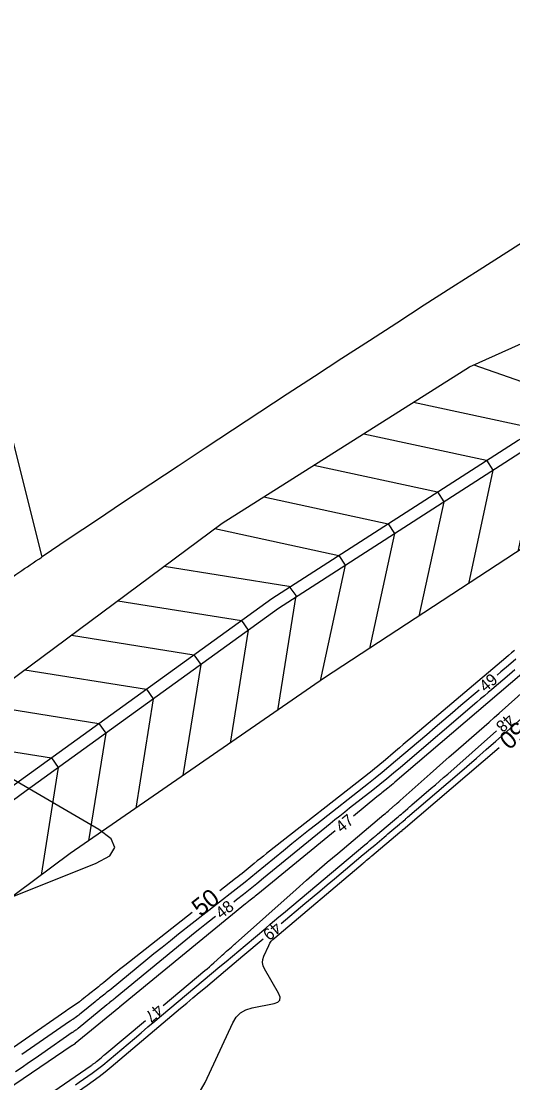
# Model space of a CAD drawing. Extents: x 2384780 to 2405861, y 547869 to 573706.
# Drawn here: x 2392601.5 to 2392685.5, y 553648.5 to 553830.1 of the extents above; entities that cross this region are included whole.
import ezdxf

# ---------------------------------------------------------------- set-up
doc = ezdxf.new("R2010")
doc.units = 0
for name, color, linetype in [('Old_Level_60', 7, 'Continuous'), ('Old_Level_61', 7, 'Continuous'), ('Old_Level_63', 7, 'Continuous'), ('Sheet Plan CELL', 7, 'Continuous')]:
    doc.layers.add(name, color=color, linetype=linetype)

msp = doc.modelspace()

# ---------------------------------------------------------------- linework, layer by layer
at = {"layer": 'Old_Level_60'}
for points in [[(2392686.04425, 553721.00125), (2392684.77, 553719.9185), (2392683.49475, 553718.837), (2392682.8395, 553718.28175)], [(2392625.80325, 553661.76), (2392632.9185, 553667.73625), (2392633.297, 553668.05775), (2392633.6715, 553668.38325), (2392634.0425, 553668.71275), (2392634.41, 553669.04675), (2392635.62225, 553670.16075), (2392635.87, 553670.3865), (2392636.11975, 553670.61), (2392636.37125, 553670.83175), (2392636.62475, 553671.051), (2392637.45575, 553671.76425), (2392637.63325, 553671.91775), (2392637.81025, 553672.07175), (2392637.98625, 553672.227), (2392638.16175, 553672.38275), (2392648.49925, 553681.6255), (2392650.25525, 553683.18325), (2392652.02375, 553684.72675), (2392653.80425, 553686.25625), (2392655.59675, 553687.77175), (2392663.5015, 553694.401), (2392663.74575, 553694.60675), (2392663.98875, 553694.8135), (2392664.231, 553695.02175), (2392664.472, 553695.231), (2392665.4205, 553696.05825), (2392665.5075, 553696.13425), (2392665.59475, 553696.21025), (2392665.68175, 553696.28625), (2392665.7685, 553696.3625), (2392666.05275, 553696.61125), (2392666.1135, 553696.6645), (2392666.174, 553696.71825), (2392666.2345, 553696.772), (2392666.295, 553696.82575), (2392671.3795, 553701.38025), (2392672.4705, 553702.3545), (2392673.56425, 553703.3255), (2392674.66125, 553704.293), (2392675.761, 553705.25725), (2392679.75275, 553708.7465), (2392680.60725, 553709.49525), (2392681.45975, 553710.246), (2392682.31025, 553710.99925), (2392683.15875, 553711.7545), (2392691.17, 553718.90425)], [(2392685.88025, 553719.15675), (2392684.9595, 553718.37575), (2392681.95025, 553715.8265), (2392681.30575, 553715.28), (2392680.66175, 553714.73275), (2392680.018, 553714.185), (2392679.375, 553713.6365), (2392666.32225, 553702.494), (2392665.15, 553701.5035), (2392663.96775, 553700.525), (2392662.77575, 553699.5585), (2392661.574, 553698.60425), (2392657.63175, 553695.506), (2392656.78875, 553694.84), (2392655.94925, 553694.16975), (2392655.113, 553693.49525), (2392654.28, 553692.8165), (2392642.94275, 553683.5295), (2392641.7925, 553682.5925), (2392640.6375, 553681.66125), (2392639.47775, 553680.73625), (2392638.313, 553679.81725), (2392637.83725, 553679.44375)], [(2392687.07525, 553718.46275), (2392665.36675, 553699.9315), (2392665.068, 553699.679), (2392664.76675, 553699.42975), (2392664.463, 553699.18325), (2392664.15675, 553698.94), (2392663.152, 553698.1505), (2392662.93725, 553697.98075), (2392662.72325, 553697.81), (2392662.51025, 553697.638), (2392662.298, 553697.46525), (2392658.2695, 553694.16525)], [(2392679.7875, 553715.69625), (2392676.655, 553713.04275), (2392675.19, 553711.8005), (2392673.72625, 553710.55675), (2392672.2635, 553709.3115), (2392670.802, 553708.06525), (2392665.48275, 553703.5245), (2392664.33825, 553702.55725), (2392663.184, 553701.602), (2392662.02, 553700.65825), (2392660.8465, 553699.7265), (2392652.02725, 553692.795), (2392650.59825, 553691.666), (2392649.17475, 553690.52975), (2392647.757, 553689.38625), (2392646.34525, 553688.23575), (2392641.74225, 553684.46525), (2392640.75375, 553683.66), (2392639.76125, 553682.85975), (2392638.7645, 553682.06475), (2392637.76375, 553681.275), (2392628.42375, 553673.9435), (2392627.013, 553672.83), (2392625.60825, 553671.709), (2392624.20975, 553670.5805), (2392622.81725, 553669.44425), (2392616.867, 553664.563), (2392616.59925, 553664.3445), (2392616.33025, 553664.12775), (2392616.06025, 553663.9125), (2392615.789, 553663.6985), (2392614.901, 553663.0025), (2392614.711, 553662.85275), (2392614.522, 553662.702), (2392614.33375, 553662.55025), (2392614.1465, 553662.39725), (2392611.75025, 553660.43125), (2392611.56075, 553660.27875), (2392611.368, 553660.13025), (2392611.17225, 553659.9855), (2392610.97375, 553659.84475), (2392610.32025, 553659.391), (2392610.18, 553659.294), (2392610.04, 553659.19675), (2392609.9, 553659.0995), (2392609.76, 553659.00225), (2392601.639, 553653.36625)], [(2392645.94425, 553675.768), (2392650.00025, 553679.1915), (2392651.26125, 553680.255), (2392652.52275, 553681.31775), (2392653.785, 553682.3795), (2392655.048, 553683.44075), (2392659.96875, 553687.5725), (2392660.456, 553687.98175), (2392660.94275, 553688.39125), (2392661.4295, 553688.80125), (2392661.916, 553689.21125), (2392663.512, 553690.558), (2392663.84875, 553690.842), (2392664.1855, 553691.12575), (2392664.5225, 553691.40925), (2392664.85975, 553691.6925), (2392666.15375, 553692.77875), (2392666.2935, 553692.897), (2392666.43225, 553693.016), (2392666.57025, 553693.136), (2392666.7075, 553693.257), (2392667.15425, 553693.65375), (2392667.25, 553693.7385), (2392667.3465, 553693.82275), (2392667.443, 553693.90675), (2392667.54025, 553693.99), (2392676.0125, 553701.23125), (2392677.67225, 553702.65675), (2392679.3255, 553704.0895), (2392680.97175, 553705.53025), (2392682.6115, 553706.9785), (2392687.95725, 553711.722)], [(2392610.778, 553648.179), (2392611.45125, 553648.64725), (2392613.649, 553650.17825), (2392614.116, 553650.5115), (2392614.57475, 553650.8555), (2392615.0255, 553651.20975), (2392615.468, 553651.57475), (2392620.86825, 553656.13425), (2392622.02575, 553657.11075), (2392623.184, 553658.08675), (2392624.34275, 553659.06175), (2392625.502, 553660.03625), (2392635.46475, 553668.40425), (2392636.5445, 553669.3115), (2392637.62375, 553670.2195), (2392638.70225, 553671.12825), (2392639.78025, 553672.03775), (2392643.30125, 553675.00925), (2392644.05575, 553675.64575), (2392644.81075, 553676.28175), (2392645.56625, 553676.9175), (2392646.32225, 553677.5525), (2392660.24075, 553689.239), (2392660.45325, 553689.4175), (2392660.6655, 553689.596), (2392660.8775, 553689.77475), (2392661.08975, 553689.9535), (2392661.78225, 553690.53775), (2392661.93075, 553690.663), (2392662.07925, 553690.788), (2392662.22775, 553690.913), (2392662.3765, 553691.038), (2392665.723, 553693.8475), (2392665.9815, 553694.06625), (2392666.2385, 553694.2865), (2392666.49375, 553694.50875), (2392666.74775, 553694.7325), (2392667.57475, 553695.467), (2392667.75225, 553695.624), (2392667.9305, 553695.78), (2392668.1095, 553695.93525), (2392668.2895, 553696.08975), (2392671.58575, 553698.907), (2392672.2905, 553699.51225), (2392672.99275, 553700.121), (2392673.692, 553700.73275), (2392674.3885, 553701.348), (2392682.702, 553708.72525)], [(2392655.175, 553691.6305), (2392641.934, 553680.7845), (2392641.729, 553680.61725), (2392641.523, 553680.45125), (2392641.31625, 553680.28625), (2392641.1085, 553680.1225), (2392640.42875, 553679.58875), (2392640.2835, 553679.47425), (2392640.13875, 553679.35875), (2392639.99475, 553679.24225), (2392639.85125, 553679.12525), (2392618.3235, 553661.465), (2392618.3115, 553661.45525), (2392618.29975, 553661.44575), (2392618.288, 553661.43625), (2392618.276, 553661.427), (2392618.237, 553661.39625), (2392618.2285, 553661.38975), (2392618.22025, 553661.383), (2392618.212, 553661.3765), (2392618.20375, 553661.36975), (2392610.767, 553655.26775), (2392610.76225, 553655.264), (2392610.7575, 553655.26025), (2392610.75275, 553655.2565), (2392610.74775, 553655.253), (2392610.7315, 553655.24175), (2392610.728, 553655.2395), (2392610.7245, 553655.237), (2392610.721, 553655.2345), (2392610.7175, 553655.23225), (2392610.4645, 553655.0565), (2392610.41025, 553655.019), (2392610.356, 553654.9815), (2392610.3015, 553654.94425), (2392610.247, 553654.907), (2392586.49075, 553638.7635)], [(2392634.69075, 553676.974), (2392634.50075, 553676.82475), (2392633.6855, 553676.18125), (2392632.87375, 553675.5335), (2392632.06575, 553674.88125), (2392631.261, 553674.22475), (2392617.59525, 553663.014), (2392617.4555, 553662.9), (2392617.315, 553662.78675), (2392617.174, 553662.67425), (2392617.0325, 553662.56275), (2392616.569, 553662.19925), (2392616.46975, 553662.12125), (2392616.371, 553662.0425), (2392616.27275, 553661.96325), (2392616.175, 553661.8835), (2392611.25875, 553657.8495), (2392611.1615, 553657.77125), (2392611.06275, 553657.69525), (2392610.9625, 553657.621), (2392610.86075, 553657.54875), (2392610.52575, 553657.3165), (2392610.454, 553657.26675), (2392610.38225, 553657.21675), (2392610.3105, 553657.167), (2392610.23875, 553657.11725), (2392605.0245, 553653.4985), (2392603.90625, 553652.7245), (2392602.786, 553651.953), (2392601.664, 553651.1845), (2392600.54, 553650.41875)], [(2392600.6475, 553639.7135), (2392601.5345, 553640.3265), (2392602.42275, 553640.938), (2392605.32575, 553642.9335), (2392605.9475, 553643.3615), (2392606.5685, 553643.7905), (2392607.18875, 553644.2205), (2392607.8085, 553644.6515), (2392612.776, 553648.112), (2392613.83125, 553648.8655), (2392614.86825, 553649.64275), (2392615.887, 553650.444), (2392616.8875, 553651.269), (2392628.7615, 553661.294), (2392629.817, 553662.18425), (2392630.87275, 553663.074), (2392631.92925, 553663.96325), (2392632.9865, 553664.85175), (2392636.4405, 553667.75275), (2392637.1805, 553668.37475), (2392637.92, 553668.997), (2392638.65925, 553669.61975), (2392639.398, 553670.243), (2392642.8875, 553673.188)], [(2392590.98725, 553636.0595), (2392613.45025, 553651.4995), (2392613.54575, 553651.56525), (2392613.64125, 553651.63125), (2392613.73675, 553651.6975), (2392613.83225, 553651.76375), (2392614.1435, 553651.9805), (2392614.2095, 553652.02775), (2392614.2745, 553652.0765), (2392614.33825, 553652.12675), (2392614.401, 553652.1785), (2392615.166, 553652.82425), (2392615.32975, 553652.9625), (2392615.49375, 553653.10075), (2392615.658, 553653.23875), (2392615.82225, 553653.37675), (2392622.74025, 553659.1875)]]:
    msp.add_lwpolyline(points, dxfattribs=at)
at = {"layer": 'Old_Level_61'}
for points in [[(2392685.77775, 553722.477), (2392685.2905, 553722.062), (2392684.80275, 553721.6475), (2392684.3145, 553721.2335), (2392668.10175, 553707.49875), (2392667.44475, 553706.9415), (2392666.78825, 553706.38375), (2392666.132, 553705.82525), (2392665.4765, 553705.26625), (2392663.33625, 553703.439), (2392662.8755, 553703.05), (2392662.411, 553702.6655), (2392661.94275, 553702.28575), (2392661.4705, 553701.91075), (2392643.44875, 553687.74675), (2392642.9175, 553687.327), (2392642.38825, 553686.90475), (2392641.86125, 553686.47975), (2392641.3365, 553686.052), (2392639.62525, 553684.65025), (2392639.258, 553684.351), (2392638.889, 553684.0535), (2392638.5185, 553683.758), (2392638.1465, 553683.46425), (2392635.44575, 553681.3445)], [(2392631.5265, 553646.11875), (2392632.926, 553648.58975), (2392637.6605, 553658.77775), (2392638.23725, 553659.73775), (2392638.9785, 553660.48825), (2392639.88425, 553661.02925), (2392640.954, 553661.36075), (2392644.7175, 553662.10175), (2392645.37175, 553662.3295), (2392645.7215, 553662.6955), (2392645.767, 553663.2), (2392645.50825, 553663.8425), (2392643.1005, 553668.01175), (2392642.86325, 553668.54725), (2392642.7665, 553669.08975), (2392642.81, 553669.63925), (2392642.994, 553670.19525), (2392643.824, 553672.02325), (2392644.02075, 553672.40075), (2392644.25525, 553672.7495), (2392644.52725, 553673.07), (2392644.83725, 553673.36175), (2392659.93675, 553686.10625), (2392660.08475, 553686.231), (2392660.23275, 553686.35575), (2392660.381, 553686.48025), (2392660.52925, 553686.60475), (2392661.0135, 553687.01125), (2392661.11725, 553687.0985), (2392661.221, 553687.18575), (2392661.3245, 553687.273), (2392661.428, 553687.3605), (2392666.19125, 553691.37925), (2392666.24125, 553691.4215), (2392666.2915, 553691.46375), (2392666.34175, 553691.506), (2392666.392, 553691.54825), (2392666.5845, 553691.71), (2392666.6055, 553691.72775), (2392666.626, 553691.74525), (2392666.64675, 553691.76325), (2392666.667, 553691.78125), (2392666.7335, 553691.84025), (2392666.748, 553691.853), (2392666.76225, 553691.8655), (2392666.77675, 553691.878), (2392666.791, 553691.8905), (2392683.19325, 553705.9095)], [(2392599.95775, 553680.3725), (2392614.34775, 553686.09475), (2392616.68775, 553687.37675), (2392617.54, 553688.77), (2392616.90475, 553690.2745), (2392614.78175, 553691.8905), (2392599.4685, 553700.82075)], [(2392630.726, 553677.63975), (2392619.234, 553668.619), (2392618.78075, 553668.26125), (2392618.3295, 553667.90125), (2392617.88, 553667.5385), (2392617.43275, 553667.1735), (2392615.97425, 553665.977), (2392615.661, 553665.7215), (2392615.3465, 553665.46775), (2392615.03025, 553665.21575), (2392614.713, 553664.9655), (2392612.97225, 553663.60125), (2392612.8215, 553663.4825), (2392612.67175, 553663.36275), (2392612.52225, 553663.2425), (2392612.37375, 553663.12125), (2392611.8895, 553662.72375), (2392611.78475, 553662.63975), (2392611.67875, 553662.55775), (2392611.57075, 553662.478), (2392611.46125, 553662.4005), (2392610.227, 553661.54375), (2392609.96225, 553661.36025), (2392609.69775, 553661.1765), (2392609.43325, 553660.993), (2392609.16875, 553660.8095), (2392588.40825, 553646.40125)]]:
    msp.add_lwpolyline(points, dxfattribs=at)
at = {"layer": 'Old_Level_63'}
msp.add_lwpolyline([(2392605.1035, 553738.50075), (2392594.60925, 553780.10375), (2392558.996, 553773.963)], dxfattribs=at)
msp.add_arc((2394828.31077, 550434.91596), 3982, 118.79726944, 123.93929722, dxfattribs=at)
msp.add_spline([(2392322.107, 553535.63125), (2392325.8135, 553538.37375), (2392329.521, 553541.1165), (2392333.2305, 553543.86075), (2392336.94225, 553546.60625), (2392340.65775, 553549.3545), (2392344.3735, 553552.102), (2392348.0935, 553554.8525), (2392351.814, 553557.6025), (2392355.53775, 553560.35425), (2392359.26675, 553563.109), (2392362.9945, 553565.86175), (2392366.727, 553568.61725), (2392370.46275, 553571.3735), (2392374.19675, 553574.1275), (2392377.936, 553576.8845), (2392381.68125, 553579.644), (2392385.42425, 553582.4005), (2392389.17375, 553585.1605), (2392392.926, 553587.92025), (2392396.6795, 553590.6795), (2392400.43925, 553593.44125), (2392404.19925, 553596.2015), (2392407.96325, 553598.96225), (2392411.72825, 553601.7215), (2392415.49925, 553604.48325), (2392419.27425, 553607.24525), (2392423.0475, 553610.00375), (2392426.82675, 553612.76425), (2392430.6105, 553615.525), (2392434.39825, 553618.286), (2392438.18925, 553621.04675), (2392441.984, 553623.807), (2392445.781, 553626.566), (2392449.57925, 553629.32275), (2392453.38325, 553632.08075), (2392457.19475, 553634.84075), (2392461.00575, 553637.5965), (2392464.82025, 553640.352), (2392468.64175, 553643.10825), (2392472.46475, 553645.8625), (2392476.2925, 553648.61625), (2392480.12425, 553651.36875), (2392483.961, 553654.12075), (2392487.79725, 553656.8685), (2392491.6425, 553659.619), (2392495.49, 553662.366), (2392499.34225, 553665.11275), (2392503.199, 553667.85775), (2392507.05775, 553670.6), (2392510.9275, 553673.34525), (2392514.7955, 553676.08425), (2392518.669, 553678.82275), (2392522.5455, 553681.55825), (2392526.4285, 553684.29325), (2392530.31675, 553687.027), (2392534.2075, 553689.7575), (2392538.10875, 553692.48975), (2392542.00975, 553695.216), (2392545.91125, 553697.93775), (2392549.823, 553700.661), (2392553.73875, 553703.381), (2392557.66125, 553706.10025), (2392561.58625, 553708.81525), (2392565.51625, 553711.52775), (2392569.452, 553714.238), (2392573.39075, 553716.9445), (2392577.34025, 553719.652), (2392581.29, 553722.353), (2392585.24325, 553725.0505), (2392589.20675, 553727.74825), (2392593.1735, 553730.4415), (2392597.14325, 553733.13), (2392601.12125, 553735.8175), (2392605.02475, 553738.44775)], degree=3, dxfattribs=at)
at = {"layer": 'Sheet Plan CELL'}
for points in [[(2393008.398, 553927.17025), (2392961.427, 553902.4275), (2392917.51975, 553878.505), (2392871.181, 553852.58075), (2392828.0225, 553827.3345), (2392788.076, 553796.64125), (2392737.2995, 553772.17825), (2392695.18775, 553745.21125), (2392653.36, 553717.816), (2392609.89525, 553687.7595), (2392569.78325, 553657.869), (2392527.365, 553625.7965), (2392487.79375, 553595.2155), (2392448.41025, 553564.38), (2392409.161, 553533.36375)], [(2392399.88375, 553545.903), (2392439.06575, 553577.01), (2392478.7045, 553607.50025), (2392518.175, 553638.21775), (2392560.9795, 553670.484), (2392601.23525, 553700.1685), (2392644.36625, 553731.39125), (2392686.40225, 553758.4725), (2392731.9095, 553780.314), (2392779.46625, 553811.242), (2392821.895, 553837.72625), (2392864.53775, 553863.847), (2392910.385, 553891.363), (2392954.08625, 553915.6555)], [(2392401.07325, 553544.29525), (2392440.25525, 553575.40225), (2392479.894, 553605.8925), (2392519.36475, 553636.60975), (2392562.12425, 553668.84375), (2392602.38, 553698.52825), (2392645.471, 553729.72375), (2392687.507, 553756.805), (2392733.0145, 553778.646), (2392780.48225, 553809.51925), (2392822.91075, 553836.0035), (2392865.55375, 553862.124), (2392911.35525, 553889.61425), (2392955.05675, 553913.9065)], [(2392391.61975, 553557.07225), (2392430.4875, 553588.60425), (2392470.201, 553618.9935), (2392510.01325, 553649.249), (2392553.45175, 553681.27075), (2392592.80775, 553712.2445), (2392635.855, 553744.2385), (2392678.09775, 553771.00725), (2392724.3275, 553791.7585), (2392772.89875, 553822.38), (2392815.1775, 553849.11825), (2392857.30175, 553876.11875), (2392903.20675, 553904.299)], [(2392678.864, 553771.35125), (2392698.7075, 553764.3785), (2392698.7075, 553764.3785), (2392698.7075, 553764.3785), (2392699.57525, 553762.57025), (2392692.96375, 553743.75475)], [(2392668.55825, 553764.96225), (2392689.457, 553760.4405), (2392689.457, 553760.4405), (2392689.457, 553760.4405), (2392690.543, 553758.7545), (2392686.362, 553739.43075)], [(2392660.03425, 553759.5605), (2392681.0375, 553755.01625), (2392681.0375, 553755.01625), (2392681.0375, 553755.01625), (2392682.1235, 553753.33025), (2392677.92, 553733.9015)], [(2392651.5105, 553754.15925), (2392672.618, 553749.592), (2392672.618, 553749.592), (2392672.618, 553749.592), (2392673.704, 553747.906), (2392669.4775, 553728.37225)], [(2392642.98625, 553748.7575), (2392664.1985, 553744.168), (2392664.1985, 553744.168), (2392664.1985, 553744.168), (2392665.2845, 553742.482), (2392661.0355, 553722.843)], [(2392634.62125, 553743.3215), (2392655.779, 553738.74375), (2392655.779, 553738.74375), (2392655.779, 553738.74375), (2392656.865, 553737.05775), (2392652.59325, 553717.31375)], [(2392625.96525, 553736.888), (2392647.2505, 553733.479), (2392647.2505, 553733.479), (2392647.2505, 553733.479), (2392648.4265, 553731.8545), (2392645.2835, 553712.231)], [(2392618.02575, 553730.98725), (2392639.1375, 553727.60625), (2392639.1375, 553727.60625), (2392639.1375, 553727.60625), (2392640.3135, 553725.9815), (2392637.21825, 553706.65375)], [(2392610.08675, 553725.08675), (2392631.02475, 553721.73325), (2392631.02475, 553721.73325), (2392631.02475, 553721.73325), (2392632.20075, 553720.10875), (2392629.1525, 553701.07625)], [(2392602.14725, 553719.186), (2392622.91175, 553715.86025), (2392622.91175, 553715.86025), (2392622.91175, 553715.86025), (2392624.088, 553714.23575), (2392621.087, 553695.49875)], [(2392594.208, 553713.28525), (2392614.799, 553709.98725), (2392614.799, 553709.98725), (2392614.799, 553709.98725), (2392615.975, 553708.36275), (2392613.02175, 553689.9215)], [(2392586.57075, 553707.336), (2392606.68625, 553704.1145), (2392606.68625, 553704.1145), (2392606.68625, 553704.1145), (2392607.86225, 553702.48975), (2392604.90775, 553684.043)]]:
    msp.add_lwpolyline(points, dxfattribs=at)

# ---------------------------------------------------------------- texts
at = {"layer": 'Old_Level_60'}
for s, rotation, p in [('49', 40.2698444, (2392680.8305, 553715.26925)), ('48', 221.5848861, (2392684.659, 553711.79875)), ('47', 39.3221306, (2392656.24725, 553691.21625)), ('48', 38.1300389, (2392635.69875, 553676.49375)), ('49', 220.1651167, (2392644.902, 553676.197)), ('47', 220.0273306, (2392624.726, 553662.16125))]:
    msp.add_text(s, height=2, rotation=rotation, dxfattribs=at).set_placement(p)
at = {"layer": 'Old_Level_61'}
for rotation, p in [(221.0048306, (2392686.268, 553710.545)), (38.1300389, (2392632.15425, 553676.85375))]:
    msp.add_text('50', height=3, rotation=rotation, dxfattribs=at).set_placement(p)

doc.saveas('drawing.dxf')
